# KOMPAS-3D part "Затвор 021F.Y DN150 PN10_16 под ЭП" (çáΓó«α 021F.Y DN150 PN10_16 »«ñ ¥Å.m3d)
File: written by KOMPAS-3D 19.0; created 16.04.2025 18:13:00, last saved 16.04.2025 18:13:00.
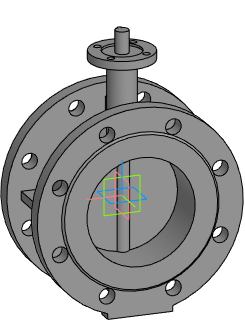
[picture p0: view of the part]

Document properties: Автор: Евгений; Полное имя файла: E:\Dendor Работа Сачек\3D для проекитирвщиков\1.6 Тип 021F.Y Затвор дисковый поворотный фланцевый\stp_Тип 021F.Y Затвор  DN40 PN10_16 под ЭП\Затвор 021F.Y DN150 PN10_16 под ЭП.m3d

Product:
- Part/product: Затвор 021F.Y DN150 PN10_16 под ЭП

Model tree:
1. Операция без истории:1  (labels: Затвор 021F.Y DN150 PN10_16 под ЭП)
